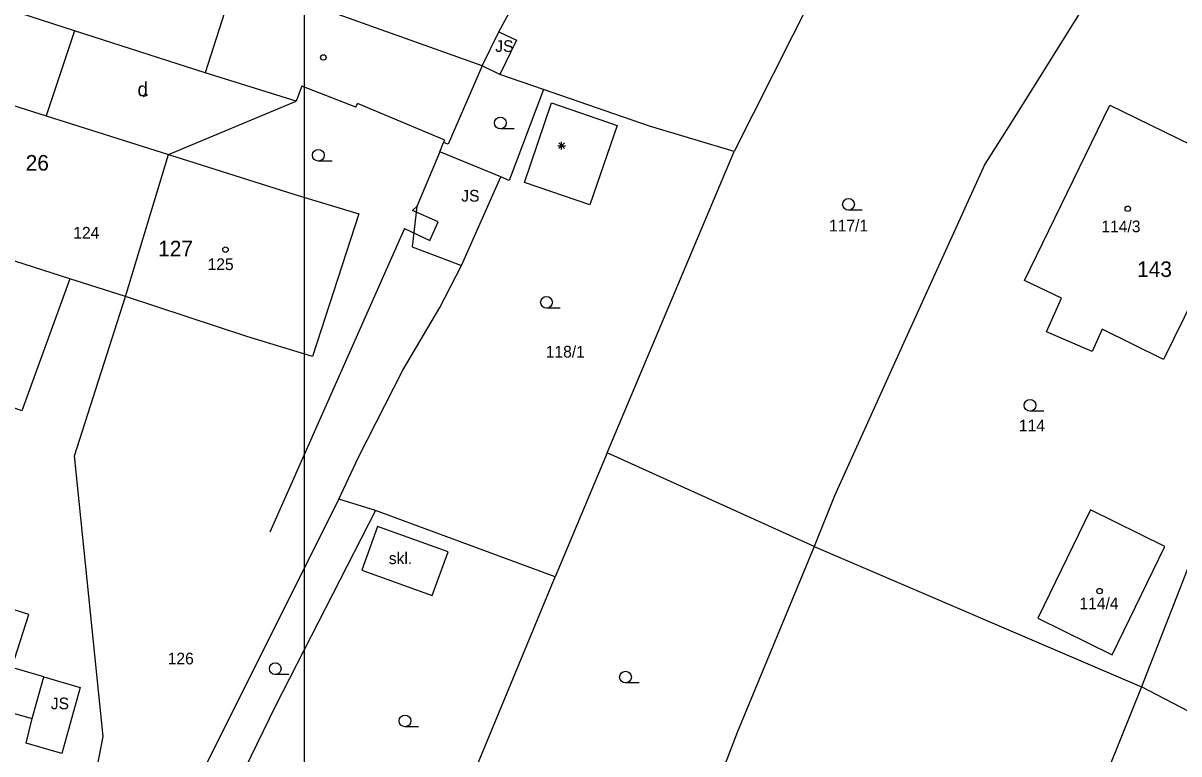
# Model space of a CAD drawing. Extents: x -836615 to -835459, y -1070675 to -1070205.
# Drawn here: x -836521.2 to -836447, y -1070416.5 to -1070369.7 of the extents above; entities that cross this region are included whole.
import ezdxf

# ---------------------------------------------------------------- set-up
doc = ezdxf.new("R2010")
doc.units = 0
for name, color, linetype in [('BodPole_body', 7, 'Continuous'), ('Budovy_hranice', 7, 'Continuous'), ('Budovy_kody', 7, 'Continuous'), ('OstPloch_hranice', 7, 'Continuous'), ('OstPloch_kody', 7, 'Continuous'), ('RuianAdr_popis', 7, 'Continuous'), ('RuianPar_popis', 7, 'Continuous'), ('Stavby_hr_stav', 7, 'Continuous'), ('Stavby_kody', 7, 'Continuous'), ('Stavby_linie', 7, 'Continuous')]:
    doc.layers.add(name, color=color, linetype=linetype)

msp = doc.modelspace()

# ---------------------------------------------------------------- linework, layer by layer
at = {"layer": 'BodPole_body'}
msp.add_lwpolyline([(-836503.12, -1070278.67), (-836206.12, -1070278.67), (-836206.12, -1070488.67), (-836503.12, -1070488.67)], close=True, dxfattribs=at)
at = {"layer": 'Budovy_hranice'}
for p, q in [((-836491.71, -1070372.41), (-836506.52, -1070367.12)), ((-836491.71, -1070372.41), (-836493.88, -1070377.44)), ((-836499.82, -1070375.05), (-836503.28, -1070373.72)), ((-836499.82, -1070375.05), (-836499.7, -1070374.83)), ((-836494.11, -1070377.17), (-836499.7, -1070374.83)), ((-836451.44, -1070374.93), (-836442.21, -1070379.44)), ((-836494.18, -1070377.33), (-836494.11, -1070377.17)), ((-836493.88, -1070377.44), (-836494.18, -1070377.33)), ((-836514.6, -1070387.21), (-836511.83, -1070378.09)), ((-836511.83, -1070378.09), (-836503.8, -1070380.64)), ((-836442.21, -1070379.44), (-836447.98, -1070391.25)), ((-836503.8, -1070380.64), (-836499.62, -1070381.9)), ((-836499.62, -1070381.9), (-836502.6, -1070391.06)), ((-836506.82, -1070389.78), (-836514.6, -1070387.21)), ((-836502.6, -1070391.06), (-836506.82, -1070389.78))]:
    msp.add_line(p, q, dxfattribs=at)
for points in [[(-836506.52, -1070367.12), (-836507.53, -1070366.76), (-836509.49, -1070372.86), (-836517.87, -1070370.16), (-836527.63, -1070367.01), (-836525.81, -1070361.26), (-836525.01, -1070358.74), (-836522.15, -1070359.6), (-836521.9, -1070358.76), (-836519.88, -1070359.35), (-836520.14, -1070360.2), (-836514.12, -1070362.01), (-836514.92, -1070364.66), (-836510.71, -1070366), (-836508.7, -1070360.55), (-836509.64, -1070360.18), (-836508.16, -1070356.49), (-836510.89, -1070355.34), (-836509.51, -1070352.17), (-836502.34, -1070355.64), (-836503.65, -1070358.81), (-836503.28, -1070358.96), (-836506.52, -1070367.12)], [(-836514.6, -1070387.21), (-836518.17, -1070386.07), (-836522.86, -1070384.58), (-836527.53, -1070383.09), (-836528.16, -1070385.07), (-836532.84, -1070383.54), (-836532.27, -1070381.59), (-836535.86, -1070380.44), (-836532.8, -1070371.47), (-836519.68, -1070375.61), (-836511.83, -1070378.09)], [(-836503.28, -1070373.72), (-836503.65, -1070374.67), (-836509.49, -1070372.86)], [(-836483.05, -1070376.23), (-836484.8, -1070381.33), (-836489, -1070379.89), (-836487.25, -1070374.79), (-836483.05, -1070376.23)], [(-836447.98, -1070391.25), (-836451.92, -1070389.29), (-836452.57, -1070390.74), (-836455.49, -1070389.47), (-836454.54, -1070387.32), (-836456.9, -1070386.18), (-836451.44, -1070374.93)], [(-836518.17, -1070386.07), (-836521.26, -1070394.54), (-836526.09, -1070392.78), (-836524.39, -1070388.48), (-836522.86, -1070384.58)], [(-836456.06, -1070407.83), (-836451.29, -1070410.18), (-836447.89, -1070403.24), (-836452.68, -1070400.88), (-836456.06, -1070407.83)], [(-836524.03, -1070413.31), (-836520.58, -1070414.27), (-836519.83, -1070411.6), (-836521.9, -1070410.99), (-836520.81, -1070407.61), (-836524.38, -1070406.47), (-836525.83, -1070410.99), (-836523.53, -1070411.73), (-836524.03, -1070413.31)]]:
    msp.add_lwpolyline(points, dxfattribs=at)
at = {"layer": 'Budovy_kody'}
for p, q in [((-836486.433, -1070377.707), (-836486.787, -1070377.353)), ((-836486.433, -1070377.353), (-836486.787, -1070377.707)), ((-836486.61, -1070377.78), (-836486.61, -1070377.28)), ((-836486.86, -1070377.53), (-836486.36, -1070377.53)), ((-836496.18, -1070381.69), (-836495.9, -1070381.44)), ((-836494.54, -1070382.42), (-836496.18, -1070381.69)), ((-836495.07, -1070383.61), (-836494.54, -1070382.42)), ((-836496.7, -1070382.84), (-836505.34, -1070402.33)), ((-836496.7, -1070382.84), (-836495.07, -1070383.61))]:
    msp.add_line(p, q, dxfattribs=at)
for centre in [(-836501.9, -1070371.87), (-836450.28, -1070381.58), (-836508.18, -1070384.2), (-836452.09, -1070406.1)]:
    msp.add_circle(centre, 0.175, dxfattribs=at)
at = {"layer": 'OstPloch_hranice'}
msp.add_line((-836494.43, -1070377.92), (-836494.18, -1070377.33), dxfattribs=at)
at = {"layer": 'OstPloch_kody'}
for p, q in [((-836489.665, -1070376.45), (-836490.54, -1070376.45)), ((-836501.345, -1070378.52), (-836502.22, -1070378.52)), ((-836467.325, -1070381.67), (-836468.2, -1070381.67)), ((-836486.705, -1070387.95), (-836487.58, -1070387.95)), ((-836455.675, -1070394.56), (-836456.55, -1070394.56)), ((-836504.115, -1070411.45), (-836504.99, -1070411.45)), ((-836481.635, -1070411.99), (-836482.51, -1070411.99)), ((-836495.785, -1070414.8), (-836496.66, -1070414.8))]:
    msp.add_line(p, q, dxfattribs=at)
msp.add_lwpolyline([(-836513.449, -1070374.36), (-836513.449, -1070374.365), (-836513.448, -1070374.371), (-836513.44, -1070374.375), (-836513.423, -1070374.373), (-836513.393, -1070374.364), (-836513.345, -1070374.343), (-836513.277, -1070374.307), (-836513.184, -1070374.254)], dxfattribs=at)
for centre in [(-836490.54, -1070376.075), (-836502.22, -1070378.145), (-836468.2, -1070381.295), (-836487.58, -1070387.575), (-836456.55, -1070394.185), (-836504.99, -1070411.075), (-836482.51, -1070411.615), (-836496.66, -1070414.425)]:
    msp.add_ellipse(centre, major_axis=(0.375, 0), ratio=0.999999, dxfattribs=at)
at = {"layer": 'Stavby_hr_stav'}
for points in [[(-836491.71, -1070372.41), (-836490.64, -1070370.23), (-836489.5, -1070370.76), (-836490.58, -1070372.96), (-836491.71, -1070372.41)], [(-836494.43, -1070377.92), (-836495.9, -1070381.44), (-836496.2, -1070384.02), (-836493.04, -1070385.21), (-836490.52, -1070379.52), (-836494.43, -1070377.92)], [(-836498.42, -1070401.95), (-836499.43, -1070404.75), (-836494.91, -1070406.38), (-836493.9, -1070403.58), (-836498.42, -1070401.95)], [(-836519.83, -1070411.6), (-836517.51, -1070412.29), (-836518.69, -1070416.52), (-836520.98, -1070415.85), (-836520.58, -1070414.27)]]:
    msp.add_lwpolyline(points, dxfattribs=at)
at = {"layer": 'Stavby_linie'}
for p, q in [((-836464.69, -1070356.37), (-836475.54, -1070377.9)), ((-836490.64, -1070370.23), (-836486.05, -1070361.8)), ((-836517.87, -1070370.16), (-836519.68, -1070375.61)), ((-836511.83, -1070378.09), (-836503.65, -1070374.67)), ((-836517.87, -1070397.43), (-836514.6, -1070387.21)), ((-836516.02, -1070415.43), (-836517.87, -1070397.43)), ((-836498.55, -1070400.92), (-836500.91, -1070400.2)), ((-836470.4, -1070403.24), (-836449.39, -1070412.25)), ((-836492.95, -1070419.48), (-836487.03, -1070405.19)), ((-836516.53, -1070417.97), (-836516.02, -1070415.43))]:
    msp.add_line(p, q, dxfattribs=at)
for points in [[(-836451.09, -1070365.35), (-836457.52, -1070375.69), (-836459.45, -1070378.71), (-836464.64, -1070390.16), (-836469.09, -1070399.98), (-836470.4, -1070403.24)], [(-836483.68, -1070397.24), (-836475.54, -1070377.9), (-836480.96, -1070376.27), (-836487.78, -1070373.92), (-836490.58, -1070372.96)], [(-836487.78, -1070373.92), (-836489.97, -1070379.76), (-836490.52, -1070379.52)], [(-836435.05, -1070376.27), (-836438.54, -1070384.68), (-836445.25, -1070401.61), (-836449.39, -1070412.25)], [(-836500.91, -1070400.2), (-836499.66, -1070397.56), (-836496.79, -1070391.92), (-836494.43, -1070387.9), (-836493.04, -1070385.21)], [(-836470.4, -1070403.24), (-836483.68, -1070397.24), (-836487.03, -1070405.19), (-836498.55, -1070400.92)], [(-836511.08, -1070420.6), (-836510.63, -1070419.69), (-836500.91, -1070400.2)], [(-836498.55, -1070400.92), (-836505, -1070413.5), (-836508.49, -1070420.71), (-836509.95, -1070423.73)], [(-836470.4, -1070403.24), (-836475.34, -1070415.17), (-836478.04, -1070422.2), (-836479.19, -1070425.44), (-836481.8, -1070432.85), (-836476.93, -1070434.4), (-836473.21, -1070423.9), (-836478.04, -1070422.2)], [(-836449.39, -1070412.25), (-836456.32, -1070429.46), (-836463.2, -1070446.07), (-836469.22, -1070461.85), (-836476.75, -1070482.14), (-836479.99, -1070490.54)], [(-836407.72, -1070434.26), (-836415.3, -1070430.25), (-836428, -1070423.55), (-836445.87, -1070414.08), (-836449.39, -1070412.25)]]:
    msp.add_lwpolyline(points, dxfattribs=at)

# ---------------------------------------------------------------- texts
at = {"layer": 'OstPloch_kody'}
msp.add_text('d', height=0.9, dxfattribs=at).set_placement((-836513.825, -1070374.36))
at = {"layer": 'RuianAdr_popis'}
for s, p in [('26', (-836521, -1070379.13)), ('127', (-836512.5, -1070384.63)), ('143', (-836449.679, -1070385.952))]:
    msp.add_text(s, height=1, dxfattribs=at).set_placement(p)
at = {"layer": 'RuianPar_popis'}
for s, p in [('117/1', (-836469.453, -1070383.032)), ('114/3', (-836451.973, -1070383.082)), ('124', (-836517.95, -1070383.49)), ('125', (-836509.33, -1070385.51)), ('118/1', (-836487.63, -1070391.12)), ('114', (-836457.265, -1070395.854)), ('114/4', (-836453.379, -1070407.261)), ('126', (-836511.89, -1070410.8))]:
    msp.add_text(s, height=0.75, dxfattribs=at).set_placement(p)
at = {"layer": 'Stavby_kody'}
for s, p in [('JS', (-836490.87, -1070371.52)), ('JS', (-836493.05, -1070381.12)), ('skl.', (-836497.7, -1070404.37)), ('JS', (-836519.39, -1070413.68))]:
    msp.add_text(s, height=0.75, dxfattribs=at).set_placement(p)

doc.saveas('drawing.dxf')
